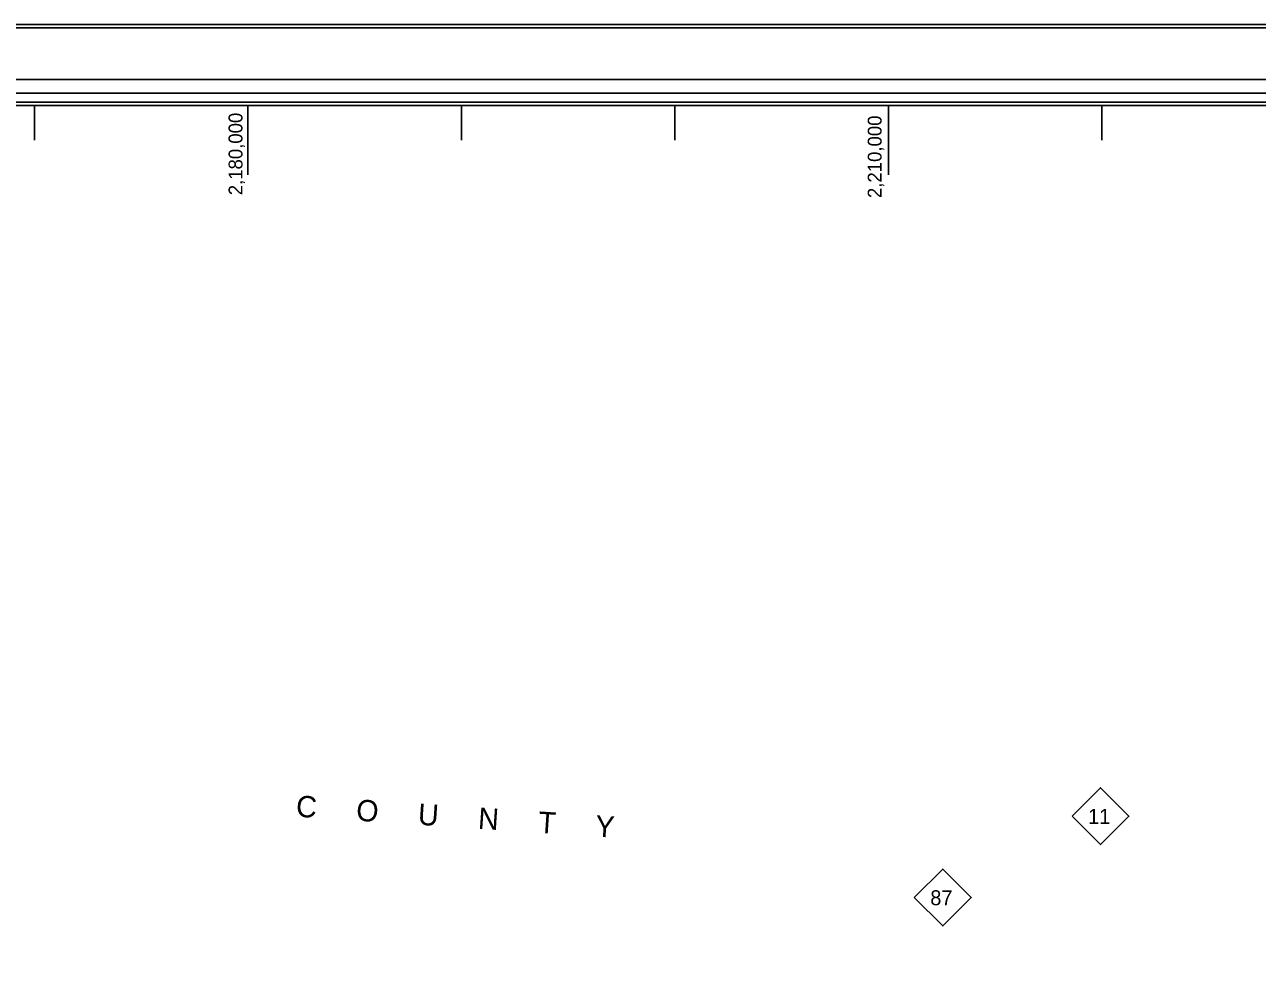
# Model space of a CAD drawing. Extents: x 5197761 to 5514561, y 1890130 to 2080942.
# Drawn here: x 5400329 to 5458064, y 2030252 to 2074930 of the extents above; entities that cross this region are included whole.
import ezdxf

# ---------------------------------------------------------------- set-up
doc = ezdxf.new("R2010")
doc.units = 0
for name, color, linetype in [('Exist Road Primary NC Shield CELL', 7, 'Continuous'), ('Exist Road Primary NC Shield Number Label', 7, 'Continuous'), ('Map Preparation Base StatePlane Tick Label', 7, 'Continuous'), ('Map Preparation Base StatePlane Tick Mark', 7, 'Continuous'), ('Map Preparation Border Antique Large Shape', 7, 'Continuous'), ('Map Preparation Border Antique Small Shape', 7, 'Continuous'), ('Map Preparation Border Black Inside Shape', 7, 'Continuous'), ('Map Preparation Border Black Middle Shape', 7, 'Continuous'), ('Map Preparation Border Black Outside Shape', 7, 'Continuous'), ('Map Preparation County Outside Label', 7, 'Continuous')]:
    doc.layers.add(name, color=color, linetype=linetype)

msp = doc.modelspace()

# ---------------------------------------------------------------- linework, layer by layer
at = {"layer": 'Exist Road Primary NC Shield CELL'}
for points in [[(5449388, 2037849), (5450720, 2039181), (5452052, 2037849), (5450720, 2036517)], [(5441997, 2034037), (5443329, 2035369), (5444661, 2034037), (5443329, 2032705)]]:
    msp.add_lwpolyline(points, close=True, dxfattribs=at)
at = {"layer": 'Map Preparation Base StatePlane Tick Mark'}
for p, q in [((5400787, 2069519), (5400787, 2071145)), ((5410787, 2067894), (5410787, 2071145)), ((5420787, 2069519), (5420787, 2071145)), ((5430787, 2069519), (5430787, 2071145)), ((5440787, 2067894), (5440787, 2071145)), ((5450787, 2069519), (5450787, 2071145))]:
    msp.add_line(p, q, dxfattribs=at)
at = {"layer": 'Map Preparation Border Antique Large Shape'}
msp.add_lwpolyline([(5197907, 2074783), (5207205, 2074783), (5207205, 1892697), (5512539, 1892697), (5512539, 2072359), (5207205, 2072359), (5207205, 2074783), (5514414, 2074783), (5514414, 1890276), (5197907, 1890276)], close=True, dxfattribs=at)
at = {"layer": 'Map Preparation Border Antique Small Shape'}
msp.add_lwpolyline([(5207791, 2071720), (5208220, 2071720), (5208220, 1893712), (5511524, 1893712), (5511524, 2071291), (5208220, 2071291), (5208220, 2071720), (5207791, 2071720), (5511953, 2071720), (5511953, 1893283), (5208220, 1893283), (5207791, 1893283)], close=True, dxfattribs=at)
at = {"layer": 'Map Preparation Border Black Inside Shape'}
msp.add_lwpolyline([(5208220, 2071291), (5511524, 2071291), (5511524, 1893712), (5208366, 1893712), (5208366, 1893858), (5511378, 1893858), (5511378, 2071145), (5208366, 2071145), (5208366, 1893858), (5208366, 1893712), (5208220, 1893712), (5208220, 1893858)], close=True, dxfattribs=at)
at = {"layer": 'Map Preparation Border Black Middle Shape'}
msp.add_lwpolyline([(5207205, 2072359), (5512539, 2072359), (5512539, 1892697), (5511953, 1892697), (5207791, 1892697), (5207791, 1893283), (5511953, 1893283), (5511953, 2071720), (5207791, 2071720), (5207791, 1892697), (5207205, 1892697)], close=True, dxfattribs=at)
at = {"layer": 'Map Preparation Border Black Outside Shape'}
msp.add_lwpolyline([(5197761, 2074930), (5514561, 2074930), (5514561, 1890130), (5197907, 1890130), (5197907, 1890276), (5514414, 1890276), (5514414, 2074783), (5197907, 2074783), (5197907, 1890130), (5197761, 1890130)], close=True, dxfattribs=at)

# ---------------------------------------------------------------- texts
at = {"layer": 'Exist Road Primary NC Shield Number Label'}
for s, p in [('11', (5450136, 2037490)), ('87', (5442746, 2033678))]:
    msp.add_text(s, height=700, dxfattribs=at).set_placement(p)
at = {"layer": 'Map Preparation Base StatePlane Tick Label'}
for s, p in [('2,180,000', (5410531, 2066937)), ('2,210,000', (5440466, 2066806))]:
    msp.add_text(s, height=650, rotation=90, dxfattribs=at).set_placement(p)
at = {"layer": 'Map Preparation County Outside Label'}
msp.add_text('C     O     U     N     T     Y', height=1000, rotation=356.19941, dxfattribs=at).set_placement((5413018, 2037829))

doc.saveas('drawing.dxf')
